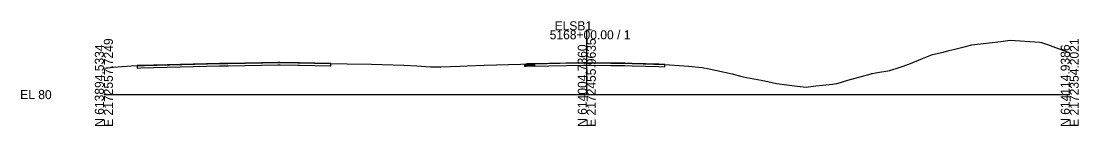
# Model space of a CAD drawing. Extents: x -26 to 1303, y -3010 to 12033.
# Drawn here: x -25.7 to 302.8, y -2009.7 to -1977.2 of the extents above; entities that cross this region are included whole.
import ezdxf

# ---------------------------------------------------------------- set-up
doc = ezdxf.new("R2010")
doc.units = 0
for name, color, linetype in [('RD_GPK_XS_Cell', 7, 'Continuous'), ('RD_XS_Base', 7, 'Continuous'), ('RD_XS_ExGround', 7, 'Continuous'), ('RD_XS_ExPaveRet', 7, 'Continuous'), ('RD_XS_Pave', 7, 'Continuous'), ('RD_XS_PaveOvlay_CP', 7, 'Continuous')]:
    doc.layers.add(name, color=color, linetype=linetype)

msp = doc.modelspace()

# ---------------------------------------------------------------- linework, layer by layer
at = {"layer": 'RD_GPK_XS_Cell'}
for p, q in [((150, -2000), (150, -1980)), ((0, -2000), (150, -2000)), ((150, -2000), (300, -2000))]:
    msp.add_line(p, q, dxfattribs=at)
at = {"layer": 'RD_XS_Base'}
for p, q in [((130.73, -1990.78), (131.23, -1990.77)), ((130.73, -1991.28), (130.73, -1990.78)), ((130.73, -1990.81), (130.73, -1990.81)), ((131.23, -1990.77), (133.72, -1990.69)), ((131.23, -1990.77), (131.23, -1990.77)), ((131.22, -1991.27), (130.73, -1991.28)), ((133.72, -1991.19), (131.22, -1991.27)), ((133.72, -1991.13), (133.72, -1991.19))]:
    msp.add_line(p, q, dxfattribs=at)
at = {"layer": 'RD_XS_ExGround'}
msp.add_lwpolyline([(0, -1991.77), (0.79, -1991.67), (1.17, -1991.63), (2.84, -1991.43), (8.44, -1991.09), (10.3, -1990.97), (12.58, -1990.91), (36.11, -1990.33), (38.46, -1990.28), (54.77, -1989.98), (60.2, -1990.11), (70.49, -1990.34), (75.62, -1990.42), (83.12, -1990.56), (86.44, -1990.68), (93.17, -1990.88), (97.26, -1991.09), (101.41, -1991.32), (103.25, -1991.38), (104.68, -1991.37), (110.66, -1991.11), (112.8, -1991.02), (118.15, -1990.84), (129.51, -1990.5), (133.72, -1990.38), (141.74, -1990.23), (149.51, -1990.08), (157.52, -1990.18), (161.56, -1990.24), (164.05, -1990.31), (174.23, -1990.6), (180.19, -1991.07), (181.61, -1991.18), (185.86, -1991.52), (187.98, -1991.99), (195.13, -1993.5), (198.2, -1994.35), (199.56, -1994.66), (204.17, -1995.48), (206.21, -1995.89), (208.97, -1996.5), (215.31, -1997.31), (218.1, -1997.66), (221.12, -1997.3), (226.31, -1996.69), (227.57, -1996.54), (227.74, -1996.5), (231.06, -1995.53), (238.37, -1993.5), (238.51, -1993.45), (238.72, -1993.39), (239.71, -1993.23), (244.09, -1992.45), (247.33, -1991.41), (250, -1990.5), (254.3, -1988.77), (257.34, -1987.57), (260.68, -1986.82), (262.48, -1986.3), (264.27, -1985.91), (267.2, -1985.14), (269.61, -1984.55), (278.63, -1983.45), (281.48, -1983.11), (290.75, -1983.73), (291.23, -1983.76), (293.1, -1984.46), (300, -1987)], dxfattribs=at)
at = {"layer": 'RD_XS_ExPaveRet'}
for p, q in [((70.49, -1990.34), (70.35, -1990.33)), ((161.77, -1990.24), (161.56, -1990.24)), ((164.05, -1990.31), (161.77, -1990.24)), ((172.39, -1990.54), (164.05, -1990.31)), ((174.23, -1990.6), (172.39, -1990.54))]:
    msp.add_line(p, q, dxfattribs=at)
for points in [[(60.75, -1990.12), (60.22, -1990.11), (54.79, -1989.98), (54.77, -1989.98), (54.77, -1989.98), (54.73, -1989.98), (54.02, -1990), (38.76, -1990.28), (38.55, -1990.28), (36.11, -1990.33), (35.96, -1990.33), (11.48, -1990.94), (10.3, -1990.97), (10.3, -1990.97), (10.3, -1990.97), (10.3, -1990.97), (10.3, -1990.97), (10.3, -1991.68), (10.3, -1991.72), (10.3, -1991.72), (10.3, -1991.72), (10.3, -1991.72), (10.3, -1991.72), (11.48, -1991.69), (35.96, -1991.08), (36.11, -1991.08), (38.55, -1991.03), (38.76, -1991.03), (54.02, -1990.75), (54.73, -1990.74), (54.77, -1990.73), (54.77, -1990.73), (54.79, -1990.73), (60.22, -1990.86), (60.75, -1990.87), (70.25, -1991.08), (70.49, -1991.09), (70.49, -1991.05), (70.49, -1990.34), (70.25, -1990.33), (60.75, -1990.12)], [(54.73, -1989.98), (54.02, -1990), (38.76, -1990.28), (38.46, -1990.28), (36.11, -1990.33), (35.96, -1990.33), (12.58, -1990.91), (11.48, -1990.94), (10.3, -1990.97), (10.3, -1990.97), (10.3, -1990.97)], [(10.3, -1990.97), (10.3, -1991.68), (10.3, -1991.72), (10.3, -1991.72), (10.3, -1991.72), (11.48, -1991.69), (35.96, -1991.08), (36.11, -1991.08), (38.55, -1991.03), (38.76, -1991.03), (54.02, -1990.75), (54.73, -1990.74), (54.77, -1990.73), (54.77, -1990.73), (54.79, -1990.73), (60.22, -1990.86), (60.75, -1990.87), (70.25, -1991.08), (70.49, -1991.09), (70.49, -1991.05), (70.49, -1990.34)], [(54.77, -1989.98), (54.77, -1989.98), (54.73, -1989.98)], [(60.47, -1990.12), (60.22, -1990.11), (60.2, -1990.11), (54.79, -1989.98), (54.77, -1989.98)], [(70.35, -1990.33), (70.25, -1990.33), (60.75, -1990.12), (60.47, -1990.12)], [(174.23, -1990.6), (172.39, -1990.54), (164.05, -1990.31), (161.77, -1990.24), (161.56, -1990.24), (161.22, -1990.23), (157.52, -1990.18), (150, -1990.09), (149.85, -1990.09), (149.51, -1990.08), (149.48, -1990.08), (148.95, -1990.09), (138.25, -1990.29), (133.72, -1990.38), (133.72, -1990.38), (133.72, -1990.89), (133.72, -1991.13), (133.72, -1991.13), (138.25, -1991.04), (148.95, -1990.84), (149.48, -1990.83), (149.51, -1990.83), (149.85, -1990.84), (150, -1990.84), (157.52, -1990.93), (161.22, -1990.98), (161.56, -1990.99), (161.77, -1990.99), (164.05, -1991.06), (172.39, -1991.29), (174.23, -1991.35), (174.23, -1991.35), (174.23, -1991.11), (174.23, -1990.6), (174.23, -1990.6)], [(148.77, -1990.1), (138.25, -1990.29), (133.72, -1990.38), (133.72, -1990.89), (133.72, -1991.13), (138.25, -1991.04), (148.95, -1990.84), (149.48, -1990.83), (149.51, -1990.83), (149.85, -1990.84), (150, -1990.84), (157.52, -1990.93), (161.22, -1990.98), (161.56, -1990.99), (161.77, -1990.99), (164.05, -1991.06), (172.39, -1991.29), (174.23, -1991.35), (174.23, -1991.35), (174.23, -1991.11), (174.23, -1990.6)], [(157.52, -1990.18), (150, -1990.09), (149.85, -1990.09), (149.51, -1990.08), (149.51, -1990.08), (149.48, -1990.08), (148.95, -1990.09), (148.77, -1990.1)], [(161.56, -1990.24), (161.22, -1990.23), (157.52, -1990.18)]]:
    msp.add_lwpolyline(points, dxfattribs=at)
at = {"layer": 'RD_XS_Pave'}
for p, q in [((133.73, -1990.38), (131.23, -1990.45)), ((131.23, -1990.45), (131.23, -1990.45)), ((131.23, -1990.45), (131.23, -1990.61)), ((133.72, -1990.54), (131.23, -1990.61)), ((131.23, -1990.61), (133.72, -1990.54)), ((131.23, -1990.61), (131.23, -1990.61)), ((131.23, -1990.61), (131.23, -1990.77)), ((131.23, -1990.61), (131.23, -1990.61)), ((131.23, -1990.61), (131.23, -1990.61)), ((131.23, -1990.77), (133.72, -1990.69)), ((131.23, -1990.77), (131.23, -1990.77)), ((131.23, -1990.77), (131.23, -1990.77))]:
    msp.add_line(p, q, dxfattribs=at)
at = {"layer": 'RD_XS_PaveOvlay_CP'}
for p in [(133.73, -1990.38), (131.23, -1990.45)]:
    msp.add_line(p, (131.23, -1990.45), dxfattribs=at)

# ---------------------------------------------------------------- texts
at = {"layer": 'RD_GPK_XS_Cell'}
for s, p in [('ELSB1', (140, -1980)), ('5168+00.00 / 1', (138.48, -1982.8)), ('EL 80', (-26, -2001.4))]:
    msp.add_text(s, height=2.8, dxfattribs=at).set_placement(p)
for s, p in [('E 2172557.7249', (2.8, -2010)), ('E 2172455.9635', (152.8, -2010)), ('E 2172354.2021', (302.8, -2010)), ('N 613894.5334', (0, -2010)), ('N 614004.7360', (150, -2010)), ('N 614114.9386', (300, -2010))]:
    msp.add_text(s, height=2.8, rotation=90, dxfattribs=at).set_placement(p)

doc.saveas('drawing.dxf')
